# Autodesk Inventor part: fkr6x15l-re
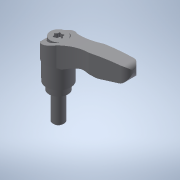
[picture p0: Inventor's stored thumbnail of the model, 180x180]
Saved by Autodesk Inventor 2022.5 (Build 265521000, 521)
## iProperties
Created: 2017-09
Part Number: fkr6x15l-re
Material: 一般
Document SubType Name: Modeling
Designer: imaocorp
Density: 1 g/cm^3
Appearance: 既定
Author: imaocorp
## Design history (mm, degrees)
node "fkr6x15l-re.x_t1"
node "fkr6x15l-re"
node "Base1"
